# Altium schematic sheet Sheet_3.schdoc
size 258 x 192 mm
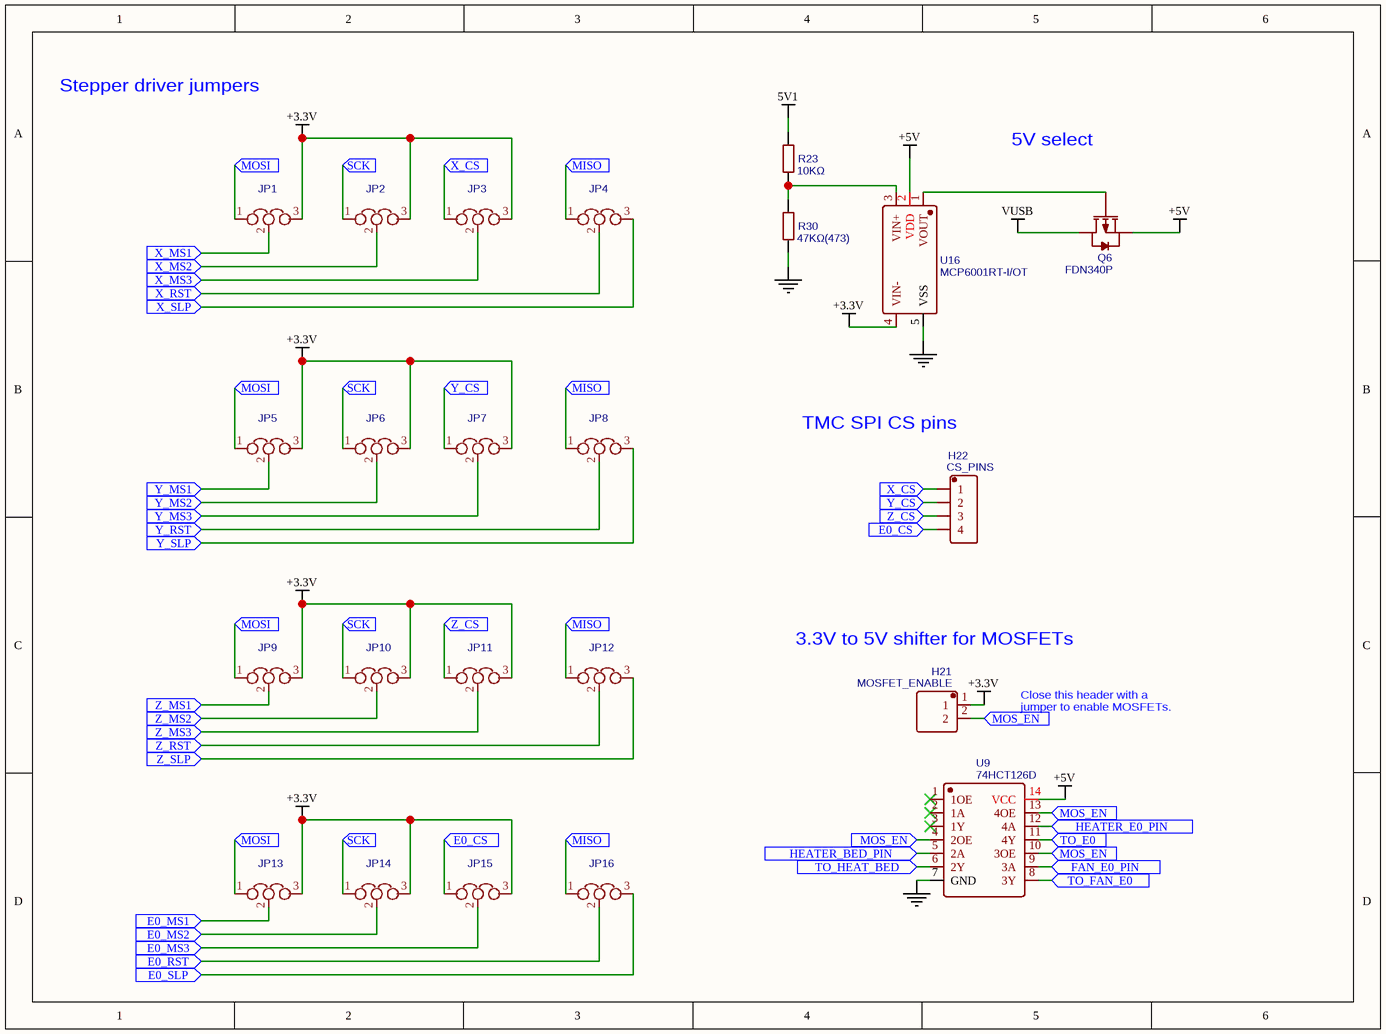
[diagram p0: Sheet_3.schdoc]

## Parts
H21  MOSFET_ENABLE  [210S-1X2P]
H22  CS_PINS  [DIP-1X4P-2.54MM-M]
JP1  JP_X_MS1  [HDR-3X1/2.54]  (value not drawn)
JP2  JP_X_MS2  [HDR-3X1/2.54]  (value not drawn)
JP3  JP_X_MS3  [HDR-3X1/2.54]  (value not drawn)
JP4  JP_X_RST  [HDR-3X1/2.54]  (value not drawn)
JP5  JP_Y_MS1  [HDR-3X1/2.54]  (value not drawn)
JP6  JP_Y_MS2  [HDR-3X1/2.54]  (value not drawn)
JP7  JP_Y_MS3  [HDR-3X1/2.54]  (value not drawn)
JP8  JP_Y_RST  [HDR-3X1/2.54]  (value not drawn)
JP9  JP_Z_MS1  [HDR-3X1/2.54]  (value not drawn)
JP10  JP_Z_MS2  [HDR-3X1/2.54]  (value not drawn)
JP11  JP_Z_MS3  [HDR-3X1/2.54]  (value not drawn)
JP12  JP_Z_RST  [HDR-3X1/2.54]  (value not drawn)
JP13  JP_E0_MS1  [HDR-3X1/2.54]  (value not drawn)
JP14  JP_E0_MS2  [HDR-3X1/2.54]  (value not drawn)
JP15  JP_E0_MS3  [HDR-3X1/2.54]  (value not drawn)
JP16  JP_E0_RST  [HDR-3X1/2.54]  (value not drawn)
Q6  FDN340P  [SOT-23(SOT-23-3)]
R23  10KΩ  [0805]
R30  47KΩ(473)  [0805]
U9  74HCT126D  [SOIC-14_150MIL]
U16  MCP6001RT-I/OT  [SOT-23-5]

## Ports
E0_CS, E0_MS1, E0_MS2, E0_MS3, E0_RST, E0_SLP, FAN_E0_PIN, HEATER_BED_PIN, HEATER_E0_PIN, MISO, MOS_EN, MOSI, SCK, TO_E0, TO_FAN_E0, TO_HEAT_BED, X_CS, X_MS1, X_MS2, X_MS3, X_RST, X_SLP, Y_CS, Y_MS1, Y_MS2, Y_MS3, Y_RST, Y_SLP, Z_CS, Z_MS1, Z_MS2, Z_MS3, Z_RST, Z_SLP

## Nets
5V1: R23.2
+3.3V: H21.1 JP1.3 JP2.3 JP3.3 JP5.3 JP6.3 JP7.3 JP9.3 JP10.3 JP11.3 JP13.3 JP14.3 JP15.3 U16.4(VIN-)
+5V: Q6.2(S) U9.14(VCC) U16.2(VDD)
GND: R30.2 U9.7(GND) U16.5(VSS)
VUSB: Q6.3(D)
E0_CS: H22.4 JP15.1 ; port E0_CS
E0_MS1: JP13.2 ; port E0_MS1
E0_MS2: JP14.2 ; port E0_MS2
E0_MS3: JP15.2 ; port E0_MS3
E0_RST: JP16.2 ; port E0_RST
E0_SLP: JP16.3 ; port E0_SLP
FAN_E0_PIN: U9.9(3A) ; port FAN_E0_PIN
HEATER_BED_PIN: U9.5(2A) ; port HEATER_BED_PIN
HEATER_E0_PIN: U9.12(4A) ; port HEATER_E0_PIN
MISO: JP4.1 JP8.1 JP12.1 JP16.1 ; port MISO
MOS_EN: H21.2 U9.4(2OE) U9.10(3OE) U9.13(4OE) ; port MOS_EN
MOSI: JP1.1 JP5.1 JP9.1 JP13.1 ; port MOSI
SCK: JP2.1 JP6.1 JP10.1 JP14.1 ; port SCK
TO_E0: U9.11(4Y) ; port TO_E0
TO_FAN_E0: U9.8(3Y) ; port TO_FAN_E0
TO_HEAT_BED: U9.6(2Y) ; port TO_HEAT_BED
X_CS: H22.1 JP3.1 ; port X_CS
X_MS1: JP1.2 ; port X_MS1
X_MS2: JP2.2 ; port X_MS2
X_MS3: JP3.2 ; port X_MS3
X_RST: JP4.2 ; port X_RST
X_SLP: JP4.3 ; port X_SLP
Y_CS: H22.2 JP7.1 ; port Y_CS
Y_MS1: JP5.2 ; port Y_MS1
Y_MS2: JP6.2 ; port Y_MS2
Y_MS3: JP7.2 ; port Y_MS3
Y_RST: JP8.2 ; port Y_RST
Y_SLP: JP8.3 ; port Y_SLP
Z_CS: H22.3 JP11.1 ; port Z_CS
Z_MS1: JP9.2 ; port Z_MS1
Z_MS2: JP10.2 ; port Z_MS2
Z_MS3: JP11.2 ; port Z_MS3
Z_RST: JP12.2 ; port Z_RST
Z_SLP: JP12.3 ; port Z_SLP
NetQ6_1: Q6.1(G) U16.1(VOUT)
NetR23_1: R23.1 R30.1 U16.3(VIN+)

Not connected (* = marked no-connect by the designer): U9 1(1OE)* 2(1A)* 3(1Y)*

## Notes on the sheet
- Stepper driver jumpers
- 5V select
- TMC SPI CS pins
- 3.3V to 5V shifter for MOSFETs
- (near U9) Close this header with a
  jumper to enable MOSFETs.

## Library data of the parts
H21 = MOSFET_ENABLE: BOM_Manufacturer: Ckmtw; BOM_Manufacturer Part: 210S-1*2P L=11.6MMGold-plated black; Contributor: LCSC
H22 = CS_PINS: BOM_Manufacturer: Ckmtw; BOM_Manufacturer Part: 210S-1*4P L=11.6MMGold-plated black; Contributor: LCSC
JP1 = JP_X_MS1: Contributor: KiCad
JP2 = JP_X_MS2: Contributor: KiCad
JP3 = JP_X_MS3: Contributor: KiCad
JP4 = JP_X_RST: Contributor: KiCad
JP5 = JP_Y_MS1: Contributor: KiCad
JP6 = JP_Y_MS2: Contributor: KiCad
JP7 = JP_Y_MS3: Contributor: KiCad
JP8 = JP_Y_RST: Contributor: KiCad
JP9 = JP_Z_MS1: Contributor: KiCad
JP10 = JP_Z_MS2: Contributor: KiCad
JP11 = JP_Z_MS3: Contributor: KiCad
JP12 = JP_Z_RST: Contributor: KiCad
JP13 = JP_E0_MS1: Contributor: KiCad
JP14 = JP_E0_MS2: Contributor: KiCad
JP15 = JP_E0_MS3: Contributor: KiCad
JP16 = JP_E0_RST: Contributor: KiCad
Q6 = FDN340P: BOM_Manufacturer: FAIRCHILD
R23 = 10KΩ: BOM_Manufacturer: YAGEO; BOM_Manufacturer Part: RC0805JR-0710KL; nameAlias: Value
R30 = 47KΩ(473): BOM_Manufacturer: YAGEO; BOM_Manufacturer Part: RC0805JR-0747KL; nameAlias: Value
U9 = 74HCT126D: BOM_Manufacturer: PHILIPS
U16 = MCP6001RT-I/OT: BOM_Manufacturer: MICROCHIP; Contributor: LCSC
